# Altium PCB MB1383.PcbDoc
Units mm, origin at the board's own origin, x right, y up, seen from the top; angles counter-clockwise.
Board outline 35.5 x 65 mm, 2 copper layers (Top Layer, Bottom Layer), stack 1.57 mm thick; 78 components, 49 nets, 296 pads, 64 vias.
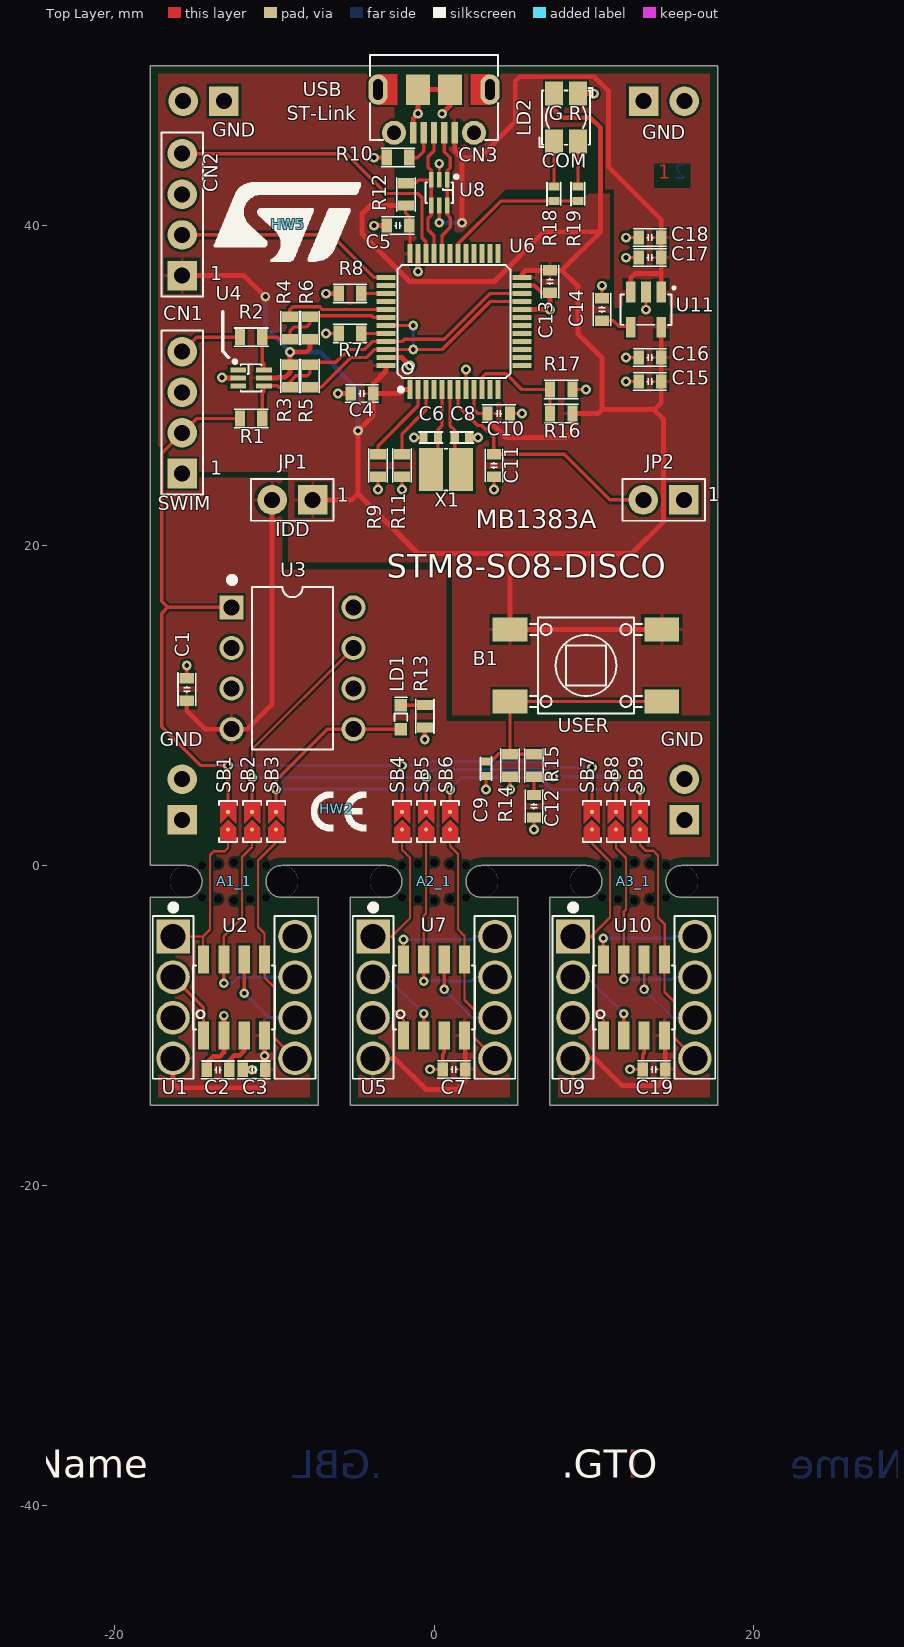
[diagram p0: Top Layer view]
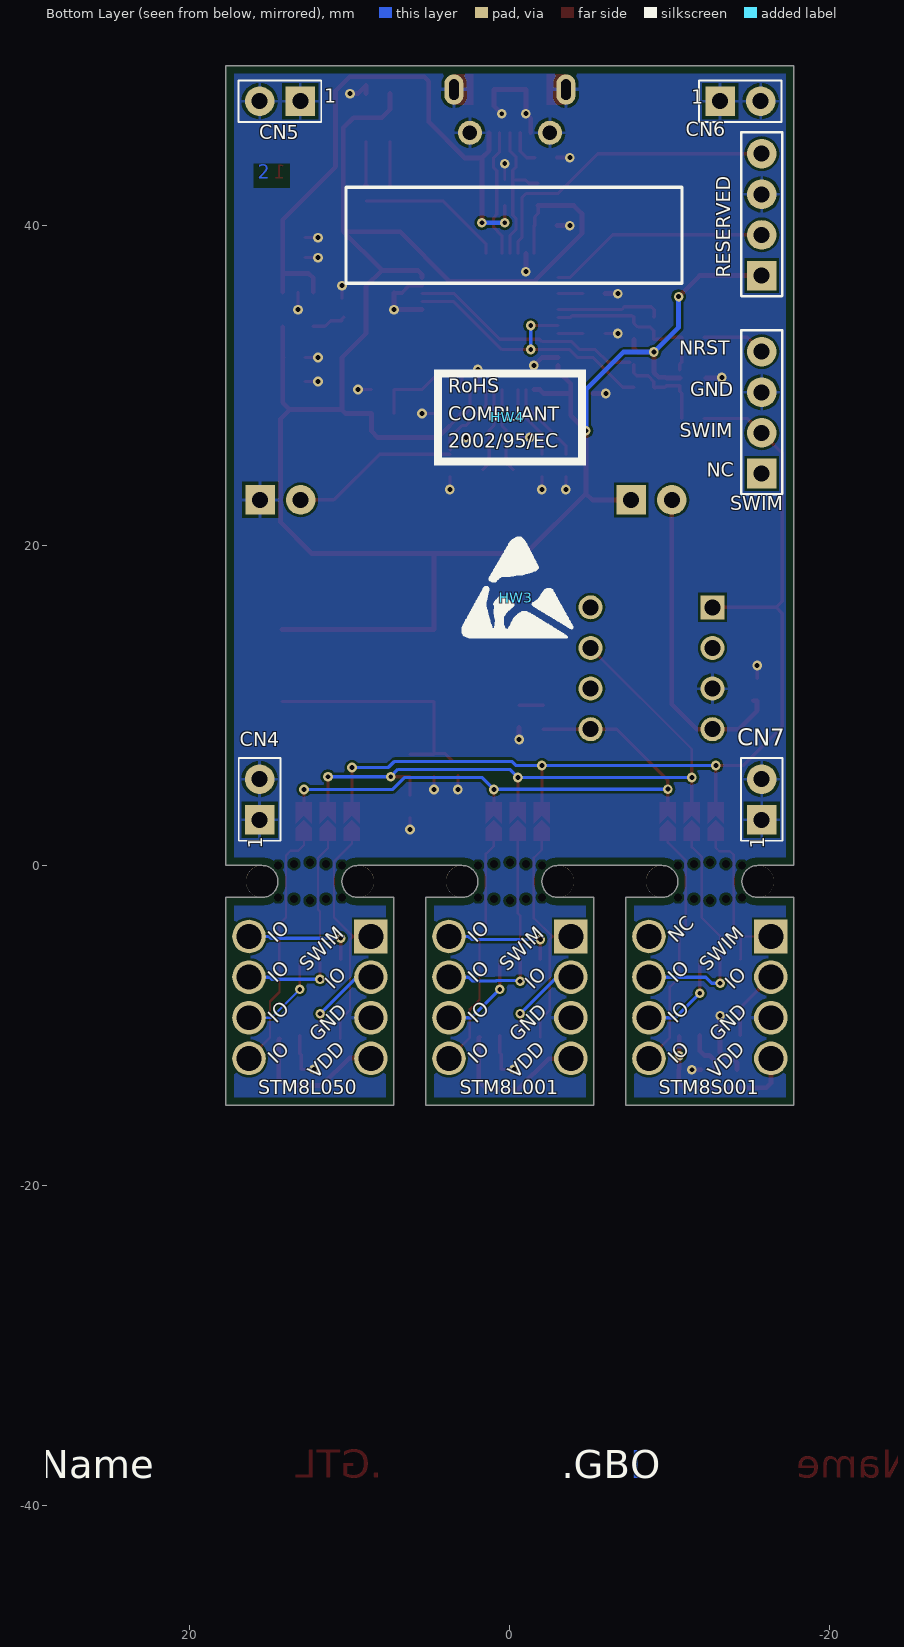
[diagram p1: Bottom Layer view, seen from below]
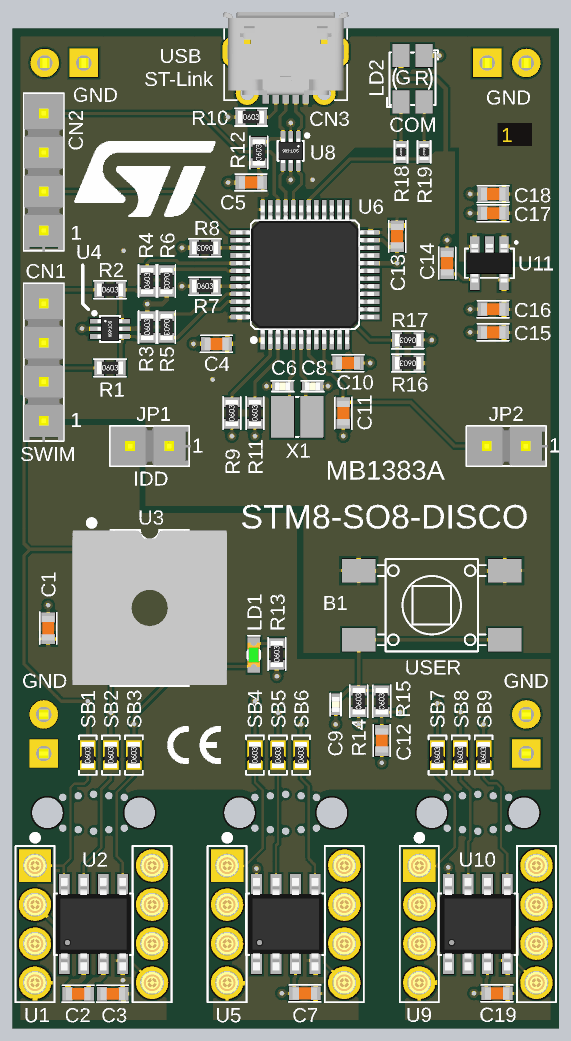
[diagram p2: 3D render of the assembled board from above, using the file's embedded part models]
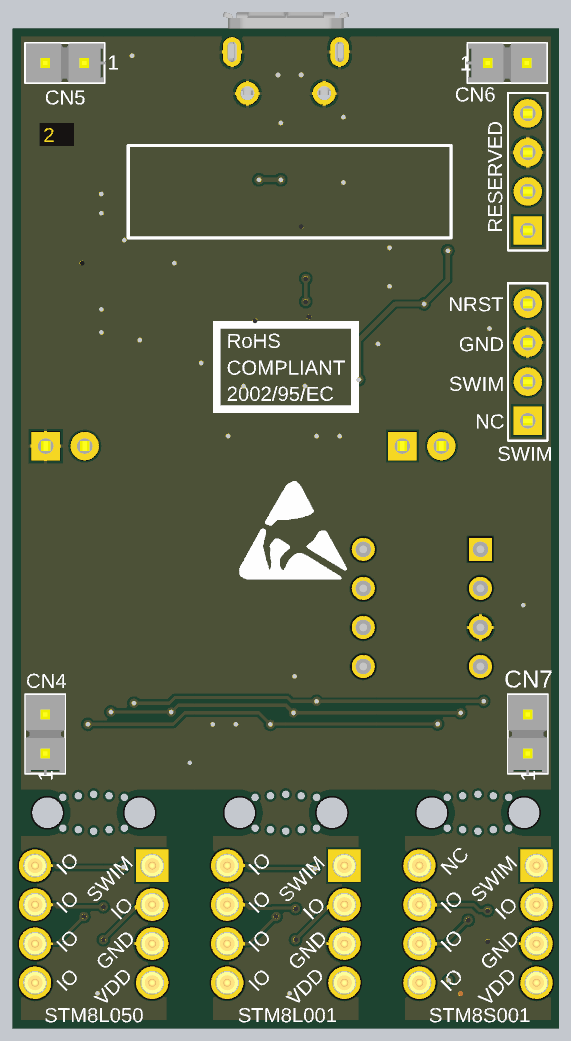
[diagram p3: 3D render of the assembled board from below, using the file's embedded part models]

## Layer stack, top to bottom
Top Solder: solder mask 0.015, Solder Resist, Dk 3.5
Top Layer: signal copper 0.035
Dielectric 1: dielectric 1.5, FR-4, Dk 4.8
Bottom Layer: signal copper 0.035
Bottom Solder: solder mask 0.015, Solder Resist, Dk 3.5

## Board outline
-17.75,-15 -17.75,-2 -15.5,-2 ccw(c-15.5,-1) -15.5,0 -17.75,0 -17.75,50 17.75,50 17.75,0 15.5,0 ccw(c15.5,-1) 15.5,-2 17.75,-2 17.75,-15 7.25,-15 7.25,-2 9.5,-2 ccw(c9.5,-1) 9.5,0 3,0 ccw(c3,-1) 3,-2 5.25,-2 5.25,-15 -5.25,-15 -5.25,-2 -3,-2 ccw(c-3,-1) -3,0 -9.5,0 ccw(c-9.5,-1) -9.5,-2 -7.25,-2 -7.25,-15

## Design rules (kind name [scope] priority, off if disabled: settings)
BoardOutlineClearance [All] p1: gap=0.2 ignorepadtopadclearanceinfootprint=FALSE except(0.5: Poly-OutlineEdge Poly-CavityEdge Poly-CutoutEdge Poly-SplitBarrior Poly-SplitContinuation)
Clearance Clearance_1 [InNetClass('MODULE') vs HasFootprint('ATTACHE')] p1: gap=0.15 ignorepadtopadclearanceinfootprint=FALSE except(0: Arc-Hole Track-Hole SMDPad-Hole THPad-Hole Via-Hole Fill-Hole Poly-Hole Region-Hole Text-Hole)
Clearance [All] p2: gap=0.15 ignorepadtopadclearanceinfootprint=FALSE except(0: Arc-Hole Track-Hole SMDPad-Hole THPad-Hole Via-Hole Fill-Hole Poly-Hole Region-Hole Text-Hole)
ComponentClearance [All] p1: gap=0.2 collisioncheckmode=3 verticalgap=0.2 showdistances=FALSE
DiffPairsRouting [All] p1: maxlimit=0.21 minlimit=0.21 mostfreqgap=0.21 toplayer_minwidth=0.21 toplayer_maxwidth=0.21 toplayer_prefwidth=0.21 bottomlayer_minwidth=0.21 bottomlayer_maxwidth=0.21 bottomlayer_prefwidth=0.21 maxuncoupledlength=12.7
HoleSize [All] p1: absolutevalues=TRUE maxlimit=10 minlimit=0.025 maxpercent=80.000 minpercent=20.000
HoleToHoleClearance [All] p1: gap=0.15 allowstackedmicrovias=TRUE
MinimumSolderMaskSliver [All] p1: minsoldermaskwidth=0.1
PlaneConnect [All] p1: planeconnectstyle=Relief reliefexpansion=0.508 reliefentries=4 reliefconductorwidth=0.21 reliefairgap=0.21
PolygonConnect PolygonConnect_via [IsVia] p1: connectstyle=Direct reliefconductorwidth=0.254 reliefentries=4 polygonreliefangle="90 Angle" airgapwidth=0.254
PolygonConnect [All] p2: connectstyle=Relief reliefconductorwidth=0.2 reliefentries=4 polygonreliefangle="90 Angle" airgapwidth=0.2
RoutingVias [All] p1: holewidth=0.3 width=0.6 viastyle="Through Hole" minholewidth=0.3 minwidth=0.6 maxholewidth=0.3 maxwidth=0.6
SilkToSilkClearance [All] p1: silktosilkclearance=0.2
SilkToSolderMaskClearance [IsPad] p1: minsilkscreentomaskgap=0.2 clearancetoexposedcopper=TRUE
SolderMaskExpansion [All] p1: expansion=0.102
UnpouredPolygon [All] p1: allowunpoured=TRUE allowshelved=TRUE
Width [All] p1: maxlimit=1 minlimit=0.15 preferedwidth=0.2 minimp=50.000000 maximp=50.000000 favimp=50.000000
21 further rules are at their usual default settings.

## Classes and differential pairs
component class U_STM8S001J3_Module: C2 C3 U1 U2
component class U_STM8L050J3_Module: C19 U9 U10
component class U_STM8L001J3_Module: C7 U5 U7
component class U_ST-LinkV2_SWIM: C4 C5 C6 C8 C10 C11 C13 C14 C15 C16 C17 C18 CN1 CN2 CN3 CN4 CN5 CN6 CN7 HW7 JP1 JP2 LD2 R1 R2 R3 R4 R5 R6 R7 R8 R9 R10 R11 R12 R16 R17 R18 R19 U4 U6 U8 U11 X1
component class U_Mechanical: HW2 HW3 HW4 HW5
component class U_Button-Led-ProgSocket: B1 C1 C9 C12 LD1 R13 R14 R15 SB1 SB2 SB3 SB4 SB5 SB6 SB7 SB8 SB9 U3
differential pair STLINK_USB_D: +STLINK_USB_D_P -STLINK_USB_D_N

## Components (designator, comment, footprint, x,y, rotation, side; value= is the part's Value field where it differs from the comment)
A1_1 "Comment" ATTACHE -12.5,-1 r0 top
A2_1 "Comment" ATTACHE 0,-1 r0 top
A3_1 "Comment" ATTACHE 12.5,-1 r0 top
B1 "SW-PUSH-CMS_BLUE" SWI_WEALTHMETAL_TD-0341_4P_BLUE 9.5,12.5 r270 top value=SW_BLUE
C1 "Capacitor" C0603 -15.45,11 r270 top value=1uF
C2 "Capacitor" C0603 -13.5,-12.775 r0 top value=1uF
C3 "Capacitor" C0603 -11.25,-12.775 r0 top value=100nF
C4 "Capacitor" C0603 -4.5,29.5 r0 top value=100nF
C5 "Capacitor" C0603 -2.25,40 r0 top value=100nF
C6 "Capacitor" C0402 -0.2,26.75 r180 top value=10pF
C7 "Capacitor" C0603 1.25,-12.75 r0 top value=100nF
C8 "Capacitor" C0402 1.75,26.75 r0 top value=10pF
C9 "Capacitor" C0402 3.25,6.05 r90 top value=10pF
C10 "Capacitor" C0603 4.05,28.25 r180 top value=100nF
C11 "Capacitor" C0603 3.75,25 r90 top value=100nF
C12 "Capacitor" C0603 6.25,3.7 r90 top value=100nF
C13 "Capacitor" C0603 7.25,36.5 r90 top value=100nF
C14 "Capacitor" C0603 10.5,34.75 r270 top value=10nF
C15 "Capacitor" C0603 13.5,30.25 r0 top value=1uF
C16 "Capacitor" C0603 13.5,31.75 r0 top value=100nF
C17 "Capacitor" C0603 13.5,38 r0 top value=100nF
C18 "Capacitor" C0603 13.5,39.25 r0 top value=1uF
C19 "Capacitor" C0603 13.75,-12.75 r0 top value=100nF
CN1 "Header 4" CON_SAMTEC_TSW-104-07-G-S -15.74,28.31 r90 top
CN2 "Header 4" CON_SAMTEC_TSW-104-07-G-S -15.74,40.685 r90 top
CN3 "USB_uB_105017.0001" CON_USBMICROB_MOLEX_105017-0001_H2P90 0,49.95 r180 top value=USB_uB_105017-0001
CN4 "Jumper_Header 2x1" CON_SAMTEC_TSW-102-07-G-S 15.65,4.125 r90 bottom value="Shunt not fitted"
CN5 "Jumper_Header 2x1" CON_SAMTEC_TSW-102-07-G-S 14.376,47.775 r0 bottom value="Shunt not fitted"
CN6 "Jumper_Header 2x1" CON_SAMTEC_TSW-102-07-G-S -14.405,47.775 r180 bottom value="Shunt not fitted"
CN7 "Jumper_Header 2x1" CON_SAMTEC_TSW-102-07-G-S -15.74,4.125 r90 bottom value="Shunt not fitted"
HW2 "Logo" LOGO_CE -6.075,3.55 r0 top value="LOGO CE"
HW3 "Logo" LOGO_MAIN_1 -0.394,16.75 r180 bottom value="LOGO ESD"
HW4 "Logo" LOGO_ROHS 0.123,28.025 r180 bottom value="LOGO ROHS"
HW5 "Logo" LOGO_STM -9.1,40.075 r0 top value="LOGO ST"
JP1 "Jumper_Header 2x1" CON_SAMTEC_TSW-102-07-G-S -8.85,22.85 r180 top value="Shunt not fitted"
JP2 "Jumper_Header 2x1" CON_SAMTEC_TSW-102-07-G-S 14.35,22.85 r180 top value="Shunt not fitted"
LD1 "LED_green" LED_0603_GREEN -2.075,9.265 r90 top value=GREEN
LD2 "LD_BICOLOR_CMS" LED_BI-GR_HSMF-A201-A00J1 8.25,46.75 r180 top
R1 "Resistor" R0603 -11.43,27.94 r0 top value=47R
R2 "Resistor" R0603 -11.43,33.02 r0 top value=47R
R3 "Resistor" R0603 -9,30.595 r90 top value=680R
R4 "Resistor" R0603 -9,33.595 r90 top value=220R
R5 "Resistor" R0603 -7.75,30.595 r270 top value=220R
R6 "Resistor" R0603 -7.75,33.595 r270 top value=680R
R7 "Resistor" R0603 -5.25,33.25 r0 top value=100K
R8 "Resistor" R0603 -5.25,35.75 r180 top value=4K7
R9 "Resistor" R0603 -3.5,25 r90 top value=10K
R10 "Resistor" R0603 -2.25,44.25 r0 top value=100K
R11 "Resistor" R0603 -2,25 r90 top value=10K
R12 "Resistor" R0603 -1.75,41.95 r90 top value=1K5
R13 "Resistor" R0603 -0.575,9.325 r90 top value=510R
R14 "Resistor" R0603 4.75,6.25 r90 top value=100K
R15 "Resistor" R0603 6.25,6.25 r90 top value=1K
R16 "Resistor" R0603 7.95,28.25 r180 top value=4K7
R17 "Resistor" R0603 7.95,29.75 r180 top value=4K7
R18 "Resistor" R0402 7.5,41.984 r270 top value=330R
R19 "Resistor" R0402 9,41.984 r270 top value=330R
SB1 "SB_ON" SOLDER-BRIDGE_R0603-0R -12.875,2.75 r90 top
SB2 "SB_ON" SOLDER-BRIDGE_R0603-0R -11.375,2.75 r90 top
SB3 "SB_ON" SOLDER-BRIDGE_R0603-0R -9.875,2.75 r90 top
SB4 "SB_OFF" SOLDER-BRIDGE_R0603-0R -2,2.75 r90 top
SB5 "SB_OFF" SOLDER-BRIDGE_R0603-0R -0.5,2.75 r90 top
SB6 "SB_OFF" SOLDER-BRIDGE_R0603-0R 1,2.75 r90 top
SB7 "SB_OFF" SOLDER-BRIDGE_R0603-0R 9.875,2.75 r90 top
SB8 "SB_OFF" SOLDER-BRIDGE_R0603-0R 11.375,2.75 r90 top
SB9 "SB_OFF" SOLDER-BRIDGE_R0603-0R 12.875,2.75 r90 top
U1 "DIL8-LYCONN-7.40X1.83" CON_LYCONN_DIL8_7P40X1P83_P254 -12.5,-8.25 r0 top value=DIL8-LYCONN--7.40X1.83
U2 "STM8S001J3M3" ICC_SO8_5X4_P127 -12.5,-8.25 r0 top
U3 "STM8-MODULE-DIL8-SOCKET" DIP8 -8.85,12.325 r0 top value=508-AG10D
U4 "USBLC6-2P6" ESD_SOT666 -11.43,30.48 r270 top
U5 "DIL8-LYCONN-7.40X1.83" CON_LYCONN_DIL8_7P40X1P83_P254 0,-8.25 r0 top value=DIL8-LYCONN--7.40X1.83
U6 "STM32F103CBT6" ICC_LQFP48_7X7_P050 1.25,34 r0 top
U7 "STM8L001J3M3" ICC_SO8_5X4_P127 0,-8.25 r0 top
U8 "USBLC6-2P6" ESD_SOT666 0.325,42.055 r180 top
U9 "DIL8-LYCONN-7.40X1.83" CON_LYCONN_DIL8_7P40X1P83_P254 12.5,-8.25 r0 top value=DIL8-LYCONN--7.40X1.83
U10 "STM8L050J3M3" ICC_SO8_5X4_P127 12.5,-8.25 r0 top
U11 "LD3985M33R" REG_SOT23-5L 13.25,34.75 r180 top
X1 "XTAL_2_PINS" CRY_NX3225GD_2P 0.75,24.75 r180 top value=NX3225GD-8.00M

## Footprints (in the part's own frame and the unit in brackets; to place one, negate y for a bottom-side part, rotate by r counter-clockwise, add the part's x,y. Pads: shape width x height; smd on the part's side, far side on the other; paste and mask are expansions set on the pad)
ATTACHE [mm]
  round 0 hole 0.5 unplated: 1(-2,-1) 1(2,1) 2(-1,-1.1) 2(1,1.1) 3(0,-1.2) 3(0,1.2) 4(-1,1.1) 4(1,-1.1) 5(-2,1) 5(2,-1)
  round 2 hole 2 unplated paste+0: 6(-3,0) 7(3,0)
C0402 [mm]
  rect 0.51x0.56 smd mask+0.05: 1(-0.45,0) 2(0.45,0)
  silkscreen extent -0.72,-0.35 0.72,0.35, body extent -0.5,-0.3 0.5,0.3, height 0.4
C0603 [mm]
  rect 0.64x0.89 smd mask+0.05: 1(-0.7,0) 2(0.7,0)
  silkscreen extent -1.05,-0.55 1.02,0.55, body extent -0.9,-0.5 0.9,0.5, height 1.4
CON_LYCONN_DIL8_7P40X1P83_P254 [mm] "DIL8 LYCONN 7.40x1.83"
  rect 2.1x2.1 hole 1.55 mask+0.05: 1(-3.81,3.81)
  round 2.1 hole 1.55: 2(-3.81,1.27) 3(-3.81,-1.27) 4(-3.81,-3.81) 5(3.81,-3.81) 6(3.81,-1.27) 7(3.81,1.27) 8(3.81,3.81)
  silkscreen extent -5.08,-5.08 5.08,5.08, body extent -4.52,-4.52 4.52,4.52, height 0.43
CON_SAMTEC_TSW-102-07-G-S [mm]
  rect 1.85x1.85 / inner round 1.85 / far side rect 1.85x1.85 hole 1 mask+0.05: 1(-1.27,0)
  round 1.85 hole 1 mask+0.05: 2(1.27,0)
  silkscreen extent -2.58,-1.3 2.58,1.3, body extent -2.67,-1.3 2.58,1.3, height 8.38
CON_SAMTEC_TSW-104-07-G-S [mm]
  rect 1.85x1.85 / inner round 1.85 / far side rect 1.85x1.85 hole 1 mask+0.05: 1(-3.81,0)
  round 1.85 hole 1 mask+0.05: 2(-1.27,0) 3(1.27,0) 4(3.81,0)
  silkscreen extent -5.12,-1.3 5.12,1.3, body extent -5.21,-1.37 5.18,1.37, height 8.38
CON_USBMICROB_MOLEX_105017-0001_H2P90 [mm]
  rect 0.4x1.35 smd mask+0.05: 1(-1.3,4.15) 2(-0.65,4.15) 3(0,4.15) 4(0.65,4.15) 5(1.3,4.15)
  round 1.5 hole 0.9 mask+0.05: 6(-2.5,4.15) 7(2.5,4.15)
  oval 1.2x1.9 hole 0.6 slot 1.3 at 90 deg mask+0.05: 8(3.5,1.45) 9(-3.5,1.45)
  rect 1.5x1.9 smd mask+0.05: 10(-1,1.45) 11(1,1.45)
  Top Layer region: 2.3,2.4 3.5,2.4 3.5,0.5 2.3,0.5 2.3,2.4
  Top Layer region: -3.5,2.4 -2.3,2.4 -2.3,0.5 -3.5,0.5 -3.5,2.4
  silkscreen extent -4,-0.7 4,4.6, body extent -4.1,-1.15 4.1,4.66, height 2.9
CRY_NX3225GD_2P [mm]
  rect 1.5x2.7 smd mask+0.05: 1(-0.95,0) 2(0.95,0)
  silkscreen extent -0.1,-1.3 0.1,1.3, body extent -1.65,-1.3 1.65,1.3, height 1
DIP8 [mm]
  rect 1.5x1.5 hole 1: 1(-3.81,3.81)
  round 1.5 hole 1: 2(-3.81,1.27) 3(-3.81,-1.27) 4(-3.81,-3.81) 5(3.81,-3.81) 6(3.81,-1.27) 7(3.81,1.27) 8(3.81,3.81)
  silkscreen extent -2.54,-5.08 2.54,5.08, body extent -5.03,-5.03 5.03,5.03, height 8
ESD_SOT666 [mm]
  rect 0.3x0.99 smd mask+0.05: 1(-0.5,-0.805) 2(0,-0.805) 3(0.5,-0.805) 4(0.5,0.805) 5(0,0.805) 6(-0.5,0.805)
  silkscreen extent -0.85,-0.65 0.85,0.65, body extent -0.85,-0.8 0.85,0.8, height 0.6
ICC_LQFP48_7X7_P050 [mm]
  rect 0.3x1.2 smd mask+0.05: 1(-2.75,-4.25) 2(-2.25,-4.25) 3(-1.75,-4.25) 4(-1.25,-4.25) 5(-0.75,-4.25) 6(-0.25,-4.25) 7(0.25,-4.25) 8(0.75,-4.25) 9(1.25,-4.25) 10(1.75,-4.25) 11(2.25,-4.25) 12(2.75,-4.25) 25(2.75,4.25) 26(2.25,4.25) 27(1.75,4.25) 28(1.25,4.25) 29(0.75,4.25) 30(0.25,4.25) 31(-0.25,4.25) 32(-0.75,4.25) 33(-1.25,4.25) 34(-1.75,4.25) 35(-2.25,4.25) 36(-2.75,4.25)
  rect 1.2x0.3 smd mask+0.05: 13(4.25,-2.75) 14(4.25,-2.25) 15(4.25,-1.75) 16(4.25,-1.25) 17(4.25,-0.75) 18(4.25,-0.25) 19(4.25,0.25) 20(4.25,0.75) 21(4.25,1.25) 22(4.25,1.75) 23(4.25,2.25) 24(4.25,2.75) 37(-4.25,2.75) 38(-4.25,2.25) 39(-4.25,1.75) 40(-4.25,1.25) 41(-4.25,0.75) 42(-4.25,0.25) 43(-4.25,-0.25) 44(-4.25,-0.75) 45(-4.25,-1.25) 46(-4.25,-1.75) 47(-4.25,-2.25) 48(-4.25,-2.75)
  silkscreen extent -3.52,-3.52 3.52,3.52, body extent -4.5,-4.5 4.5,4.5, height 1.6
ICC_SO8_5X4_P127 [mm]
  rect 0.7x1.75 smd mask+0.05: 1(-1.905,-2.375) 2(-0.635,-2.375) 3(0.635,-2.375) 4(1.905,-2.375) 5(1.905,2.375) 6(0.635,2.375) 7(-0.635,2.375) 8(-1.905,2.375)
  silkscreen extent -2.58,-2 2.58,2, body extent -2.57,-3 2.57,3, height 1.75
LED_0603_GREEN [mm]
  rect 0.8x0.8 smd mask+0.05: 1(-0.75,0) 2(0.75,0)
  silkscreen extent -0.25,-0.4 1.25,0.4, body extent -0.8,-0.4 0.8,0.4, height 0.6
LED_BI-GR_HSMF-A201-A00J1 [mm]
  rect 1.1x1.5 smd mask+0.05: 1(-0.75,-1.5) 2(-0.75,1.5) 3(0.75,1.5) 4(0.75,-1.5)
  silkscreen extent -1.65,-1.85 1.65,1.85, body extent -1.5,-1.85 1.5,1.85, height 2.1
LOGO_CE [mm]
  silkscreen extent -1.61,-1.37 1.85,1.07
LOGO_MAIN_1 [mm]
  silkscreen extent -3.36,-2.51 3.52,3.76
LOGO_ROHS [mm]
  silkscreen extent -4.63,-3.02 4.87,2.98
LOGO_STM [mm]
  silkscreen extent -4.66,-2.3 4.54,2.62
R0402 [mm]
  rect 0.51x0.7 smd mask+0.05: 1(-0.45,0) 2(0.45,0)
  silkscreen extent -0.72,-0.43 0.72,0.43, body extent -0.52,-0.3 0.52,0.3, height 0.4
R0603 [mm]
  rect 0.64x1 smd mask+0.05: 1(-0.7,0) 2(0.7,0)
  silkscreen extent -1.05,-0.58 1.05,0.58, body extent -0.9,-0.5 0.9,0.5, height 0.56
REG_SOT23-5L [mm]
  rect 0.6x1.3 smd mask+0.05: 1(-0.95,-1.1) 2(0,-1.1) 3(0.95,-1.1) 4(0.95,1.1) 5(-0.95,1.1)
  silkscreen extent -1.6,-0.95 1.6,0.97, body extent -1.52,-1.25 1.52,1.25, height 1.1
SOLDER-BRIDGE_R0603-0R [mil]
  round 10 smd paste-393.7: 1(-19.68,0) 2(23.62,0)
  Top Layer region: -5.91,19.68 13.78,0 -5.91,-19.68 47.24,-19.68 47.24,19.68 -5.91,19.68
  Top Layer region: -47.24,-19.68 -47.24,19.68 -15.75,19.68 3.94,0 -15.75,-19.68 -47.24,-19.68
  silkscreen extent -50,-23 50,23, body extent -36,-20 36,20, height 22
SWI_WEALTHMETAL_TD-0341_4P_BLUE [mm]
  rect 1.52x2.16 smd mask+0.05: 1(-2.25,-4.75) 2(-2.25,4.75) 3(2.25,-4.75) 4(2.25,4.75)
  silkscreen extent -3,-3.5 3,3.5, body extent -3,-5.15 3,5.15, height 7.55

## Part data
B1: library part MCD-00002, "Non-Open Push-Button 0.1A 24V BLUE", Manufacturer=WEALTHMETAL, Manufacturer_Part_Number=TD0341X-G01-BLU
C1 C2 C15 C18: library part MCD-00010, "Capacitor, MLCC, 1uF, 16V, X5R, 10%, 0603, T=0,8mm", Manufacturer=YAGEO, Manufacturer_Part_Number=CC0603KRX5R7BB105, Package=C0603
C3 C4 C5 C7 C10 C11 C12 C13 C16 C17 C19: library part MCD-00211, "Capacitor, MLCC, 100nF, 16V, X7R, 10%, 0603, T=0,8mm", Manufacturer=YAGEO, Manufacturer_Part_Number=CC0603KRX7R7BB104, Package=C0603
C6 C8 C9: library part MCD-00015, "Capacitor, MLCC, 10pF, 50V, NPO, 5%, 0402, T=0,5mm", Manufacturer=YAGEO, Manufacturer_Part_Number=CC0402JRNPO9BN100, Package=C0402
C14: library part MCD-00017, "Capacitor, MLCC, 10nF, 50V, X7R, 10%, 0603, T=0.8mm", Manufacturer=YAGEO, Manufacturer_Part_Number=CC0603KRX7R9BB103, Package=C0603
CN1 CN2: "Header, 4-Pin", Manufacturer=SAMTEC, Manufacturer_Part_Number=TSW-104-07-G-S
CN3: library part MCD-00028, "USB-MICRO-B, 0.65mm, RA, SMT, Bottom Mount,", Manufacturer=MOLEX, Manufacturer_Part_Number=1050170001
CN4 CN5 CN6 CN7 JP1 JP2: library part MCD-00045, "Header, 2x1, 2,54mm, VR, TH, Height 5.84mm/2.54mm", Manufacturer=SAMTEC, Manufacturer_Part_Number=TSW-102-07-x-S
HW2: library part MCD-00626, "CE logo footprint for PCB"
HW3: library part MCD-00627, "Hand ESD logo footprint for PCB", Manufacturer=n/a
HW4: library part MCD-00628, "ROHS logo footprint for PCB"
HW5: library part MCD-00625, "STMicroelectronics logo footprint for PCB", Manufacturer=n/a
LD1: library part MCD-00050, "LED, Green, 0603", Manufacturer=EVERLIGHT, Manufacturer_Part_Number=19-213SYGC/S530-E2/TR8, Package="LED 0603"
LD2: library part MCD-00051, "LED Bicolor", Alternate_Manufacturer=EVERLUCK, Alternate_Manufacturer_Part_Number=LE-RGW35280, Manufacturer="AVAGO TECHNOLOGIES", Manufacturer_Part_Number=HSMF-A201-A00J1
R1 R2: library part MCD-00482, "Resistor,47R,0603,1%,1/10W", Manufacturer=YAGEO, Manufacturer_Part_Number=RC0603FR-0747RL, Package=R0603
R3 R6: library part MCD-00508, "Resistor,680R,0603,1%,1/10W", Manufacturer=YAGEO, Manufacturer_Part_Number=RC0603FR-07680RL, Package=R0603
R4 R5: library part MCD-00428, "Resistor,220R,0603,1%,1/10W", Manufacturer=YAGEO, Manufacturer_Part_Number=RC0603FR-07220RL, Package=R0603
R7 R10 R14: library part MCD-00223, "Resistor,100K,0603,1%,1/10W", Manufacturer=YAGEO, Manufacturer_Part_Number=RC0603FR-07100KL, Package=R0603
R8 R16 R17: library part MCD-00219, "Resistor,4K7,0603,1%,1/10W", Manufacturer=YAGEO, Manufacturer_Part_Number=RC0603FR-074K7L, Package=R0603
R9 R11: library part MCD-00220, "Resistor,10K,0603,1%,1/10W", Manufacturer=YAGEO, Manufacturer_Part_Number=RC0603FR-0710KL, Package=R0603
R12: library part MCD-00217, "Resistor,1K5,0603,1%,1/10W", Manufacturer=YAGEO, Manufacturer_Part_Number=RC0603FR-071K5L, Package=R0603
R13: library part MCD-00225, "Resistor,510R,0603,1%,1/10W", Manufacturer=YAGEO, Manufacturer_Part_Number=RC0603FR-07510RL, Package=R0603
R15: library part MCD-00070, "Resistor,1K,0603,1%,1/10W", Manufacturer=YAGEO, Manufacturer_Part_Number=RC0603FR-071KL, Package=R0603
R18 R19: library part MCD-00062, "Resistor,330R,0402,1%,1/16W", Manufacturer=YAGEO, Manufacturer_Part_Number=RC0402FR-07330RL, Package=R0402
SB1 SB2 SB3: library part MCD-00071, "Solder Bridge ON"
SB4 SB5 SB6 SB7 SB8 SB9: library part MCD-00072, "Solder Bridge OFF"
U1 U5 U9: library part MCD-01221, "PCB socket DIL 8-pin", Manufacturer=LYCONN, Manufacturer_Part_Number=DIL8-LYCONN--7.40X1.83
U2: library part MCD-01218, "STM8S 8-bit MCU, 8-Kbyte Flash, 128-byte data EEPROM", Manufacturer=STMICROELECTRONICS, Package=SO8N
U3: "STM8-MODULE-DIL8-", Manufacturer="TE CONNECTIVITY / AMP", Manufacturer_Part_Number=508-AG10D
U4 U8: library part MCD-00169, "USB OTG FS ESD protection", Manufacturer=STMICROELECTRONICS
U6: library part MCD-00085, "Medium-density performance line ARM-based 32-bit MCU with 128KB Flash", Manufacturer=STMICROELECTRONICS
U7: library part MCD-01217, "STM8L 8-bit ultra-low-power microcontroller, 8-Kbyte Flash", Manufacturer=STMICROELECTRONICS, Package=SO8N
U10: library part MCD-01216, "STM8L 8-bit ultra-low-power MCU, 8-Kbyte Flash, 256-byte data EEPROM", Manufacturer=STMICROELECTRONICS, Package=SO8N
U11: library part MCD-00086, "Ultra low drop-low noise BiCMOS voltage, regulators low ESR capacitors compatible", Manufacturer=STMICROELECTRONICS
X1: library part MCD-00092, "Crystal 8Mhz, 8pF, -+50PPM, SMD", Manufacturer=NDK, Manufacturer_Part_Number="NX3225GD 8MHz EXS00A-CG04874"

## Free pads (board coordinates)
  round 0.508 on Mech16: 1(-22.05,-45.212) 1(26.797,-45.212)

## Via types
v1: diameter 0.6, hole 0.3, Top Layer to Bottom Layer, tented both sides, 64 vias

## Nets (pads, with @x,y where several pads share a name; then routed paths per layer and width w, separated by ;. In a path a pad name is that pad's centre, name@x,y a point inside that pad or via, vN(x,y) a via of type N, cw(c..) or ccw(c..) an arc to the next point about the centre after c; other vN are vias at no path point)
3V3_STLINK: B1.1 B1.2 C4.2 C5.2 C10.2 C13.2 C15.2 C16.2 CN2.1 JP1.1 LD2.4 R3.2 R6.2 R12.1 R16.1 U4.5 U6.1 U6.9 U6.24 U6.36 U6.48 U11.5 | length 151.8
  Top Layer w0.21: R12.1 -1.778,41.222 -1.778,40.767 -1.55,40.539 C5.2 -1.5,39.95 U6.36 ; U6.9 2.5,28.5 2.75,28.25 3.125,28.25 3.125,28.125 3.812,27.438
  Top Layer w0.3: CN2.1 -11.856,36.875 v1(-10.541,35.56) ; U4.5 -9.779,30.48 -9.744,30.515 -9.301,30.515 -9,30.816 R3.2 v1(-9,32.095) -8,32.095 -7.75,32.345 R6.2 ; JP1.1@-7.98,22.85 JP1.1 -5.15,22.85 -4.75,23.25 ; U6.48 -3,30.909 -3.8,30.109 C4.2 ; R12.1 -4,41.25 -4.5,40.75 -4.5,39.5 -2.5,37.5 -1.5,36.5 3.75,36.5 6.869,39.619 10.414,39.619 ; U6.1 -1.873,29.75 -2.123,29.5 C4.2 ; 3.812,27.438 4.5,26.75 8.25,26.75 8.65,27.15 R16.1 10.25,28.25 10.5,28.5 ; U6.24 5.5,36.95 5.75,37.2 C13.2 7.995,37.2 ; LD2.4 7.5,47.237 8.001,46.736 9.779,46.736 10.414,46.101 10.414,39.619 ; U11.5 14.2,31.77 14.19,31.76 C16.2 C15.2 14.2,28.925 13.775,28.5 13.75,28.5 ; B1.2 B1.1 4.75,19.5 ; -4.75,23.25 -1,19.5 4.75,19.5 ; -4.75,23.25 v1(-4.75,27.178) -3.8,28.128 C4.2 ; 4.75,19.5 12.375,19.5 14.35,21.475 14.35,27.9 13.75,28.5 ; 7.995,37.2 10.414,39.619 ; 7.995,37.2 9,36.195 9,33.25 10.5,31.75 10.5,28.5 ; 10.5,28.5 13.75,28.5
  Bottom Layer w0.3: v1(-10.541,35.56) -10.541,33.636 v1(-9,32.095) -7.095,32.095 -4.75,29.75 v1(-4.75,27.178)
5V_STLINK: C17.2 C18.2 CN3.1 U8.5 U11.1 U11.3 | length 38.4
  Top Layer w0.21: v1(0.325,40.175) U8.5
  Top Layer w0.3: CN3.1 1.3,44.674 1.75,44.224 ; v1(1.75,40.175) 1.75,44.224 ; U11.3 12.3,36.727 12.573,37 14.2,37 ; U11.1 14.2,37 ; C17.2 C17.2@14.2,38.085 ; 1.75,44.224 2.822,44.224 5.08,46.482 5.08,49.022 5.358,49.3 10.025,49.3 10.9,48.425 10.9,43.675 14.2,40.375 C18.2 C17.2@14.2,38.085 ; 14.2,37 C17.2@14.2,38.085
  Bottom Layer w0.3: v1(0.325,40.175) 1.675,40.175 v1@1.75,40.25
AIN_1: R16.2 R17.2 U6.10 | length 7
  Top Layer w0.21: U6.10 3,30.5 3.234,30.734 4.516,30.734 5.5,29.75 R17.2 R16.2
GND: C1.1 C2.1 C3.1 C4.1 C5.1 C6.2 C7.1 C8.2 C9.1 C10.1 C11.1 C12.1 C13.1 C14.1 C15.1 C16.1 C17.1 C18.1 C19.1 CN1.3 CN2.3 CN3.5 CN3.6 CN3.7 CN3.8 CN3.9 CN3.10 CN3.11 CN4.1 CN4.2 CN5.1 CN5.2 CN6.1 CN6.2 CN7.1 CN7.2 JP2.1 LD2.1 R7.1 R8.2 R9.1 R10.1 R11.1 R13.1 R14.1 R17.1 U1.3 U2.2 U3.3 U4.2 U5.3 U6.8 U6.20 U6.23 U6.35 U6.47 U7.3 U8.2 U9.3 U10.3 U11.2 | length 47.9
  Top Layer w0.15: U8.2 v1(0.325,43.875)
  Top Layer w0.21: C1.1 v1(-15.45,12.5) ; v1(-6.75,33.25) R7.1 ; v1(-3.5,23.5) R9.1 ; v1(-2,23.5) R11.1 ; v1(-1.25,26.75) C6.2 ; v1(-0.25,-12.75) C7.1 0.55,-11.787 0.635,-11.702 U7.3 ; U6.8 v1(2,31) ; C8.2 v1(2.75,26.75) ; v1(3.25,4.75) C9.1 ; v1(3.75,23.5) C11.1 ; v1(4.75,4.75) R14.1 ; C10.1 v1(5.5,28.25) ; v1(6.25,2.25) C12.1 ; R17.1 v1(9.5,29.75) ; C14.1 v1(10.5,36.25) ; v1(12,30.25) C15.1 ; v1(12,31.75) C16.1 ; v1(12,38) C17.1 ; v1(12,39.25) C18.1 ; v1(12.25,-12.75) C19.1 13.05,-11.842 13.135,-11.757 U10.3 ; v1(13.25,34.75) U11.2
  Top Layer w0.25: v1(-3.75,44.25) R10.1 ; U6.23 6.295,36.25 6.745,35.8 C13.1
  Top Layer w0.3: C2.1 -14.2,-12.324 -13.826,-11.95 -13.4,-11.95 -13.135,-11.685 U2.2 v1(-13.135,-9.385) ; v1(-13.25,30.5) -13.23,30.48 U4.2 ; C3.1 v1(-11.375,-12.775) ; v1(-6.75,35.75) R8.2 ; v1(-6,29.5) C4.1 ; v1(-3.75,40) C5.1 ; U6.47 -2,31.75 -1.75,31.5 v1(-1.5,31.25) ; CN3.5 -1.3,46.7 v1(-1,47) CN3.11 CN3.10 1,47.482 v1(0.508,46.99) ; v1(-1,37.125) U6.35 ; v1(-0.575,7.875) R13.1 ; U6.20 v1(7.25,34.75) C13.1 ; LD2.1 9,48.75 9.5,48.25 v1(10,48.25)
LED_STLINK: R18.2 R19.2 U6.30 | length 9.2
  Top Layer w0.21: U6.30 1.5,38.861 4.173,41.534 R18.2 R19.2
NetB1_3: B1.3 B1.4 C9.2 R14.2 R15.2 | length 16.6
  Top Layer w0.21: C9.2 3.564,6.5 4.064,7 R14.2@4.75,7 ; R15.2 R14.2 ; B1.4 B1.3 4.75,7.5 ; R14.2 R14.2@4.75,7 ; R14.2 4.75,7.5 ; R14.2@4.75,7 4.75,7.5
NetC2_2: C2.2 U2.3 | length 2.7
  Top Layer w0.3: C2.2 -12.8,-12.2 -12.475,-11.875 -12.15,-11.875 -11.865,-11.59 U2.3
NetC12_2: C12.2 R15.1 SB2.2 SB5.2 SB8.2 U3.7 | length 42.8
  Top Layer w0.15: -11.375,6.3 -11.375,7.26 U3.7
  Top Layer w0.21: SB2.2 -11.375,6.3 ; SB5.2 v1(-0.5,5.5) ; C12.2 R15.1 v1(7.45,5.55) ; SB8.2 v1(11.375,5.55)
  Bottom Layer w0.21: v1(-11.375,5.5) v1(-0.5,5.5) 0,6 7,6 v1(7.45,5.55) v1(11.375,5.55) v1@11.5,5.55
NetC14_2: C14.2 U11.4 | length 2.2
  Top Layer w0.21: C14.2@10.38,34.265 C14.2@10.595,34.05 ; C14.2 C14.2@10.595,34.05 ; U11.4@12.29,33.695 11.557,33.695 11.202,34.05 C14.2@10.595,34.05
NetCN1_4: CN1.4 R2.1 | length 4
  Top Layer w0.21: CN1.4 -14.84,33.02 R2.1
NetCN3_4: CN3.4 R10.2 | length 2.2
  Top Layer w0.21: R10.2 -1.05,44.25 -0.65,44.65 CN3.4
NetLD1_1: LD1.1 SB3.2 SB6.2 SB9.2 U3.5 | length 37.5
  Top Layer w0.21: SB3.2 v1(-9.875,4.775) -9.875,5.325 -6.685,8.515 U3.5 LD1.1 ; SB6.2@1,3.25 SB6.2 v1(1,4.75) ; SB9.2 v1(12.875,4.75)
  Bottom Layer w0.21: v1(-9.875,4.775) v1@1.025,4.775 ; v1(1,4.75) v1@1.025,4.775 ; v1@1.175,4.775 v1@1.025,4.775 ; v1(12.875,4.75) 7.315,4.75 6.565,5.5 1.75,5.5 v1@1.025,4.775
NetLD1_2: LD1.2 R13.2 | length 1.5
  Top Layer w0.21: LD1.2 R13.2@-0.575,10.015
NetLD2_2: LD2.2 R19.1 | length 2.7
  Top Layer w0.21: R19.1@9,42.544 LD2.2
  Top Layer w0.3: R19.1@9,42.544 R19.1@9.005,42.539
NetLD2_3: LD2.3 R18.1 | length 2.8
  Top Layer w0.21: R18.1 LD2.3
NetR7_2: R7.2 U6.44 | length 1.5
  Top Layer w0.21: R7.2 U6.44
NetR8_1: R8.1 U6.39 | length 1.5
  Top Layer w0.21: R8.1 U6.39
NetR9_2: R9.2 U6.2 | length 5.1
  Top Layer w0.21: R9.2 -3.5,26.25 -1,28.75 U6.2
NetR11_2: R11.2 U6.3 | length 4.7
  Top Layer w0.21: R11.2 -2,27 -0.5,28.5 U6.3
NetU1_2: U1.2 U2.1 | length 4.4
  Top Layer w0.21: U1.2 -14.405,-8.885 U2.1
NetU1_6: U1.6 U2.6 | length 5.9
  Top Layer w0.21: v1(-11.865,-7.99) U2.6
  Bottom Layer w0.21: v1(-11.865,-7.99) -10.335,-9.52 U1.6
NetU5_2: U5.2 U7.2 | length 5.5
  Top Layer w0.21: U7.2 v1(-0.635,-9.26)
  Bottom Layer w0.21: U5.2 -2.915,-6.98 v1(-0.635,-9.26)
NetU5_6: U5.6 U7.6 | length 5.8
  Top Layer w0.21: v1(0.635,-7.75) U7.6
  Bottom Layer w0.21: v1(0.635,-7.75) 2.405,-9.52 U5.6
NetU5_8: U5.8 U7.8 | length 7
  Top Layer w0.21: U7.8 v1(-1.905,-4.63)
  Bottom Layer w0.21: v1(-1.905,-4.63) 2.37,-4.63 2.56,-4.44 U5.8
NetU9_2: U9.2 U10.2 | length 5.5
  Top Layer w0.21: U10.2 v1(11.865,-9.265)
  Bottom Layer w0.21: U9.2 9.58,-6.98 v1(11.865,-9.265)
NetU9_6: U9.6 U10.6 | length 5.8
  Top Layer w0.15: v1(13.135,-7.75) U10.6
  Bottom Layer w0.15: v1(13.135,-7.75) 14.905,-9.52 U9.6
NetU9_8: U9.8 U10.8 | length 7.1
  Top Layer w0.21: v1(10.575,-4.55) 10.575,-5.855 U10.8
  Bottom Layer w0.21: v1(10.575,-4.55) 14.94,-4.55 15.05,-4.44 U9.8
STLINK_SWCLK: CN2.2 U6.37 | length 13.8
  Top Layer w0.21: CN2.2 -6.415,39.415 -3.75,36.75 U6.37
STLINK_SWDIO: CN2.4 U6.34 | length 19.7
  Top Layer w0.21: CN2.4 -5.495,44.495 -3,42 -1,42 -0.75,41.75 -0.75,39.25 -0.5,39 U6.34
STLINK_USB_D_N: CN3.2 U6.32 U8.1 U8.6 | length 8.1
  Top Layer w0.21: U6.32 0.5,39.362 1.025,39.887 1.025,40.5 0.825,40.7 U8.6 U8.1 0.825,43.425 1.025,43.625 1.025,44.25 0.65,44.625 CN3.2
STLINK_USB_D_P: CN3.3 R12.2 U6.33 U8.3 U8.4 | length 9.7
  Top Layer w0.21: R12.2 -1.165,42.65 -0.965,42.85 -0.185,42.85 U8.3 ; U6.33 0,39.37 -0.375,39.745 -0.375,40.45 -0.175,40.65 U8.4 U8.3 ; CN3.3 0,44.675 -0.375,44.3 -0.375,43.65 -0.175,43.45 U8.3
STLK_OSC_IN: C6.1 U6.5 X1.2 | length 5.3
  Top Layer w0.21: X1.2 0.25,25.2 C6.1 0.25,27.25 0.5,27.5 U6.5
STLK_OSC_OUT: C8.1 U6.6 X1.1 | length 5.3
  Top Layer w0.21: U6.6 1,27.5 1.3,27.2 C8.1 1.3,25.15 X1.1
STLK_RST: C11.2 JP2.2 U6.7 | length 14.9
  Top Layer w0.21: U6.7 1.5,28.75 2.75,27.5 3,27.5 3.725,26.775 C11.2@3.725,25.975 ; C11.2 8.148,25.7 10.998,22.85 JP2.2@12.655,22.85
STM8L001J3_T_SWIM: SB4.1 U5.1 U7.1 | length 15.1
  Top Layer w0.15: U5.1 -2.65,-4.44 ; SB4.1 -2,0.984 -1.5,0.484 -1.5,-3.3 -2.65,-4.45 -2.5,-4.6 -2.5,-9.025 -1.899,-9.626 U7.1@-1.899,-10.733
STM8L001J3_USER_B: SB5.1 U5.7 U7.7 | length 14.1
  Top Layer w0.15: U7.7@-0.635,-5.865 -0.635,-3.135 -0.5,-3 SB5.1
  Top Layer w0.21: v1(-0.635,-7.24) U7.7
  Bottom Layer w0.15: v1(-0.635,-7.24) v1@-0.62,-7.225
  Bottom Layer w0.21: v1@-0.62,-7.225 -0.59,-7.195 0.865,-7.195 0.895,-7.225 2.325,-7.225 2.57,-6.98 U5.7
STM8L001J3_USER_LED: SB6.1 U5.5 U7.5 | length 15.6
  Top Layer w0.15: SB6.1 1,1.225 1.5,0.725 1.5,-3.984 1.905,-4.402 U7.5 1.905,-8.405 2.5,-9 2.5,-10.75 U5.5 ; SB6.1@1,2.35 SB6.1
STM8L050J3_T_SWIM: SB7.1 U9.1 U10.1 | length 15.5
  Top Layer w0.15: U9.1 9.81,-4.44 ; SB7.1 9.875,1.375 11,0.25 11,-3.25 9.81,-4.44 ; U10.1@10.601,-10.835 10.601,-9.626 10,-9.025 10,-4.63 9.81,-4.44
STM8L050J3_USER_B: SB8.1 U9.7 U10.7 | length 14.2
  Top Layer w0.15: SB8.1 11.375,1.1 12,0.475 12,-2.75 11.871,-2.879 U10.7@11.871,-6.085
  Top Layer w0.21: v1(11.871,-7.121) U10.7@11.871,-6.085
  Bottom Layer w0.21: v1(11.871,-7.121) 14.879,-7.121 15.02,-6.98 U9.7
STM8L050J3_USER_LED: SB9.1 U9.5 U10.5 | length 16.2
  Top Layer w0.15: SB9.1 12.875,1.275 13.225,0.925 13.7,0.925 14,0.625 14,-3.25 14.411,-3.661 U10.5@14.411,-6.085 ; U10.5 14.405,-7.905 15,-8.5 15,-10.75 U9.5
STM8S001J3_T_SWIM: SB1.1 U1.1 U2.8 | length 11.1
  Top Layer w0.15: U1.1 -14.44,-4.44 ; U2.8 -14.44,-5.84 -14.44,-4.44 ; SB1.1 -12.875,1.1 -13.082,0.893 -13.757,0.893 -14,0.65 -14,-4 -14.44,-4.44
STM8S001J3_USER_B: SB2.1 U1.7 U2.7 | length 15.1
  Top Layer w0.15: U2.7@-13.25,-5.754 U2.7@-13.135,-5.869 ; U2.7 U2.7@-13.135,-5.869 ; U2.7@-13.129,-5.875 U2.7@-13.135,-5.869 ; SB2.1 -11.375,1.15 -12,0.525 -12,-3.275 -13.135,-4.41 U2.7@-13.135,-5.869
  Top Layer w0.21: v1(-13.135,-7.365) U2.7
  Bottom Layer w0.21: v1(-13.135,-7.365) -12.615,-7.365 -12.23,-6.98 U1.7
STM8S001J3_USER_LED: SB3.1 U1.5 U2.5 | length 15.7
  Top Layer w0.15: U2.5 -10.595,-4.244 -11,-3.839 -11,0.3 -9.875,1.425 SB3.1 ; U2.5@-10.589,-5.875 -10.589,-7 -10,-7.589 -10,-10.75 U1.5
SWIM: R1.2 R3.1 R5.1 U4.4 U6.22 U6.45 | length 20.9
  Top Layer w0.21: R1.2 -10.73,29.529 -10.625,29.634 U4.4 -9.779,29.98 -9.694,29.895 R3.1@-9.07,29.895 ; R3.1@-9.07,29.825 R3.1@-9.07,29.895 ; R5.1 -7.75,30.795 -7.938,30.607 -8.636,30.607 -9,30.243 R3.1 R3.1@-9.07,29.895 ; R5.1@-7.5,31.45 -6.142,31.45 -5.342,32.25 -4.35,32.25 -3.85,32.75 U6.45 -2,32.75 -1.857,32.893 0.634,32.893 3.491,35.75 U6.22
SWIM_IN: R5.2 U6.21 U6.43 U6.46 | length 18.7
  Top Layer w0.21: R5.2 -7.062,29.895 -5.207,31.75 -4.25,31.75 -3.75,32.25 U6.46 v1(-1.3,32.25) 0.5,32.25 3.5,35.25 U6.21 ; U6.43 v1(-1.3,33.75) v1@-1.25,33.75
  Bottom Layer w0.21: v1(-1.3,32.25) -1.3,33.7 v1@-1.25,33.75
SWIM_RST: R2.2 R4.1 R6.1 U4.6 U6.42 | length 10.9
  Top Layer w0.21: U4.6 -10.625,31.35 -10.73,31.455 R2.2 -9.779,33.02 -9.654,32.895 R4.1 -9,33.418 -8.763,33.655 -8.001,33.655 -7.75,33.906 R6.1 ; R6.1@-7.62,34.355 -3.875,34.355 -3.77,34.25 U6.42
SWIM_RST_IN: R4.2 U6.41 | length 6.6
  Top Layer w0.21: R4.2 -9.01,34.305 -9.01,34.74 -8.825,34.925 -7.15,34.925 -6.975,34.75 U6.41
T_SWIM: CN1.2 R1.1 SB1.2 SB4.2 SB7.2 U3.1 | length 64
  Top Layer w0.21: SB1.2 v1(-12.875,6.25) -14.6,6.25 -17.018,8.668 -17.018,15.75 -16.633,16.135 ; U3.1 -16.633,16.135 ; R1.1 -14.84,27.94 CN1.2 -17.018,25.762 -17.018,16.52 -16.633,16.135 ; SB4.2 v1(-2,6.25) ; SB7.2 v1(9.875,6.125)
  Bottom Layer w0.21: v1(-12.875,6.25) v1(-2,6.25) -0.354,6.25 -0.104,6.5 7.216,6.5 7.591,6.125 v1(9.875,6.125) v1@10,6.125
VDD: C1.2 C3.2 C7.2 C19.2 JP1.2 U1.4 U2.4 U3.4 U5.4 U7.4 U9.4 U10.4 | length 49.4
  Top Layer w0.3: U1.4 -16.31,-13.615 -16.025,-13.9 -10.875,-13.9 -10.55,-13.575 C3.2 -10.589,-12.736 v1(-10.589,-11.9) U2.4@-10.589,-10.693 ; C1.2@-15.215,10.3 C1.2 -15.45,9.675 -14.29,8.515 U3.4 -11.685,8.515 -10.12,10.08 JP1.2 ; U5.4@-3.81,-12.08 -2.42,-12.08 -0.5,-14 1.45,-14 1.95,-13.5 C7.2 1.95,-10.771 U7.4@1.911,-10.733 ; U9.4@8.69,-12.04 10.04,-12.04 11.75,-13.75 14,-13.75 14.45,-13.3 C19.2 14.45,-10.874 U10.4@14.411,-10.835
  Bottom Layer w0.3: v1@-10.629,-12.04 -10.589,-12 v1(-10.589,-11.9)
pads on no net: A1_1.1 A1_1.2 A1_1.3 A1_1.4 A1_1.5 A1_1.6 A1_1.7 A2_1.1 A2_1.2 A2_1.3 A2_1.4 A2_1.5 A2_1.6 A2_1.7 A3_1.1 A3_1.2 A3_1.3 A3_1.4 A3_1.5 A3_1.6 A3_1.7 CN1.1 U1.8 U3.2 U3.6 U3.8 U4.1 U4.3 U6.4 U6.11 U6.12 U6.13 U6.14 U6.15 U6.16 U6.17 U6.18 U6.19 U6.25 U6.26 U6.27 U6.28 U6.29 U6.31 U6.38 U6.40

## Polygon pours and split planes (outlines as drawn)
5V_STLINK on Top Layer "5V_STLINK_L01_P004" (solid, remove dead copper, pour order 4): 4.48,42.275 1.78,39.575 0,39.575 0,50.5 17.25,50.5 17.25,34.85 11.275,34.85 11.275,42.275
3V3_STLINK on Top Layer "3V3_STLINK_L01_P002" (solid, remove dead copper, pour order 2): -9.125,18.95 1.15,18.95 1.15,9.4 17.25,9.4 17.25,34.5 13.5,34.5 11,34.5 11,39.5 11,42 5,42 2.5,39.5 -2.5,39.5 -2.5,51 -17.25,51 -17.25,24.625 -9.125,24.625
VDD on Top Layer "VDD_L01_P006" (solid, remove dead copper, pour order 6): 0.75,9 0.75,18.5 -9.5,18.5 -9.5,24.225 -17.275,24.225 -17.275,-15 17.275,-15 17.275,9
GND on Bottom Layer "GND_L02_P000" (solid, remove dead copper, pour order 0): -19.75,0 -19.75,51.25 19,51.25 19,0.5 19,-14.5 7.75,-14.5 4.75,-14.5 -4.75,-14.5 -7.75,-14.5 -19.75,-14.5 -19.75,-2.5

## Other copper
Top Layer:
  pour cut-out: 13.775,43.875 13.775,42.375 16.025,42.375 16.025,43.875
  text "1" at 14.025,42.625 h1.5
  text ".Layer_Name" at -33.72,-38.864 h3
  text ".GTL" at 7.975,-38.864 h3
Bottom Layer:
  pour cut-out: 13.775,43.875 13.775,42.375 16.025,42.375 16.025,43.875
  text "2" at 15.775,42.625 h1.5
  text ".GBL" at -3.229,-38.896 h3
  text ".Layer_Name" at 38.085,-38.896 h3

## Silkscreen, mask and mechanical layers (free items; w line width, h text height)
Top Overlay:
  circle w0.254: c-2.075,29.75 r0.125
  circle w0.5: c8.7,-2.625 r0.125
  circle w0.5: c-3.8,-2.625 r0.125
  circle w0.5: c-16.3,-2.625 r0.125
  circle w0.21: c1.397,43.053 r0.1
  circle w0.21: c-12.446,31.496 r0.1
  circle w0.5: c-12.625,17.85 r0.125
  lines w0.21: -13.208,34.625 -13.208,32.131 -12.827,31.75
  lines w0.254: 15.024,36.107 ccw(c15,36.1) 15.025,36.1
  text "USB" at -8.2,47.775 h1.5
  text "ST-Link" at -9.2,46.275 h1.5
  text "GND" at -13.85,45.25 h1.5
  text "GND" at 13.025,45.075 h1.5
  text "COM" at 6.731,43.307 h1.5
  text "SWIM" at -17.268,21.883 h1.5
  text "MB1383A" at 2.6,20.675 h2
  text "IDD" at -9.912,20.275 h1.5
  text "STM8-SO8-DISCO" at -2.944,17.5 h2.5
  text "USER" at 7.747,8.001 h1.5
  text "GND" at -17.15,7.125 h1.5
  text "GND" at 14.175,7.125 h1.5
  text ".Layer_Name" at -33.72,-38.864 h3
  text ".GTO" at 7.975,-38.864 h3
Bottom Overlay:
  lines w0.15: -17.025,23.225 -17.025,33.45 -14.45,33.45 -14.45,23.225 ; -17.025,35.6 -17.025,45.825 -14.45,45.825 -14.45,35.6 ; -17,23.2 -14.475,23.2 ; -17,35.575 -14.475,35.575
  lines w0.2: -10.75,36.4 -10.75,42.4 10.25,42.4 10.25,36.4 -10.75,36.4
  text "RESERVED" at -14.075,36.75 h1.5 r270
  text "NRST" at -10.575,31.625 h1.5
  text "GND" at -11.257,29.025 h1.5
  text "SWIM" at -10.607,26.45 h1.5
  text "NC" at -12.314,24 h1.5
  text "SWIM" at -13.757,21.9 h1.5
  text "NC" at -10.625,-5.125 h1.5 r315
  text "IO" at 1.875,-5.125 h1.5 r315
  text "IO" at 14.375,-5.125 h1.5 r315
  text "SWIM" at -12.575,-6.9 h1.5 r315
  text "SWIM" at -0.075,-6.9 h1.5 r315
  text "SWIM" at 12.425,-6.9 h1.5 r315
  text "IO" at -10.625,-7.61 h1.5 r315
  text "IO" at 1.875,-7.61 h1.5 r315
  text "IO" at 14.375,-7.61 h1.5 r315
  text "IO" at -14.171,-8.03 h1.5 r315
  text "IO" at -1.671,-8.03 h1.5 r315
  text "IO" at 10.829,-8.03 h1.5 r315
  text "IO" at -10.625,-10.15 h1.5 r315
  text "IO" at 1.875,-10.15 h1.5 r315
  text "IO" at 14.375,-10.15 h1.5 r315
  text "GND" at -13.198,-11.3 h1.5 r315
  text "GND" at -0.698,-11.3 h1.5 r315
  text "GND" at 11.802,-11.3 h1.5 r315
  text "IO" at -10.625,-12.69 h1.5 r315
  text "IO" at 1.875,-12.69 h1.5 r315
  text "IO" at 14.375,-12.69 h1.5 r315
  text "VDD" at -13.106,-13.625 h1.5 r315
  text "VDD" at -0.606,-13.625 h1.5 r315
  text "VDD" at 11.894,-13.625 h1.5 r315
  text "STM8S001" at -9.298,-14.625 h1.5
  text "STM8L001" at 3.127,-14.625 h1.5
  text "STM8L050" at 15.719,-14.625 h1.5
  text ".GBO" at -3.229,-38.896 h3
  text ".Layer_Name" at 38.085,-38.896 h3
Top Paste:
  text ".Layer_Name" at -33.72,-38.864 h3
  text ".GTP" at 7.975,-38.864 h3
Bottom Paste:
  text ".GBP" at -3.229,-38.896 h3
  text ".Layer_Name" at 38.085,-38.896 h3
Top Solder:
  rectangle: 13.775,42.375 16.025,43.875
  text ".Layer_Name" at -33.72,-38.864 h3
  text ".GTS" at 7.975,-38.864 h3
Bottom Solder:
  rectangle: 13.775,42.375 16.025,43.875
  text ".GBS" at -3.229,-38.896 h3
  text ".Layer_Name" at 38.085,-38.896 h3
M1-Board Shape:
  lines w0.254: 7.25,-2 9.5,-2 ccw(c9.5,-1) 9.5,0 3,0 ccw(c3,-1) 3,-2 5.25,-2 5.25,-15 -5.25,-15 -5.25,-2 -3,-2 ccw(c-3,-1) -3,0 -9.5,0 ccw(c-9.5,-1) -9.5,-2 -7.25,-2 -7.25,-15 -17.75,-15 -17.75,-2 -15.5,-2 ccw(c-15.5,-1) -15.5,0 -17.75,0 -17.75,50 17.75,50 17.75,0 15.5,0 ccw(c15.5,-1) 15.5,-2 17.75,-2 17.75,-15 7.25,-15 7.25,-2 ; 7.25,-2 7.25,-2
M2-Board Dimensions:
  text ".Layer_Name" at -33.72,-38.864 h3
  text ".GM2" at 7.975,-38.864 h3
M14-Top Assembly:
  text ".Layer_Name" at -33.72,-38.864 h3
  text ".GM14" at 7.975,-38.864 h3
M15-Bottom Assembly:
  text ".GM15" at -3.229,-38.896 h3
  text ".Layer_Name" at 38.085,-38.896 h3
Drill Drawing:
  text ".Legend" at -42.7,61.525 h1.2
  text ".Layer_Name" at -33.72,-38.864 h3
  text ".DRL" at 7.975,-38.864 h3
M20-Top Title Box:
  circle w0.254: c44.284,-45.584 r1.3
  region: 29.806,-46.677 19.05,-46.677 20.043,-44.185 27.901,-44.185 28.35,-43.425 30.558,-45.974
  region: 43.809,-38.348 28.282,-38.348 27.588,-40.123 26.377,-41.348 24.98,-39.488 24.98,-37.837 26.123,-36.44 27.559,-36.062 43.809,-36.062
  lines w0.254: 20.043,-44.185 28.835,-44.185 25.769,-40.647 cw(c27.573,-38.703) 27.813,-36.062 44.577,-36.062 43.815,-38.348 ; 23.357,-35.815 cw(c25.783,-36.785) 26.02,-34.183 ; 23.396,-35.782 19.05,-46.677 38.373,-46.677 ccw(c38.621,-43.943) 41.171,-44.963 ; 25.136,-39.717 30.558,-45.974 ; 25.39,-39.717 30.695,-45.838 ; 25.39,-39.463 30.695,-45.584 ; 25.488,-38.348 38.481,-38.348 ; 25.517,-39.336 30.822,-45.457 ; 25.644,-39.209 30.949,-45.33 ; 25.771,-39.082 31.076,-45.203 ; 25.898,-38.955 31.203,-45.076 ; 25.953,-37.003 31.258,-43.124 ; 26.021,-34.183 45.471,-34.183 41.171,-44.96 ; 26.025,-38.828 31.276,-44.886 ; 26.025,-38.574 31.33,-44.695 ; 26.025,-38.32 31.33,-44.441 ; 26.025,-37.431 31.33,-43.552 ; 26.152,-38.193 31.457,-44.314 ; 26.152,-37.812 31.457,-43.933 ; 27.524,-44.198 ccw(c27.629,-43.663) 27.926,-43.206 ; 28.61,-38.334 ccw(c28.584,-38.902) 28.254,-39.364 30.619,-42.093 cw(c28.815,-44.036) 29.548,-46.585 ; 34.892,-46.473 37.781,-38.094 ; 35.114,-46.423 37.983,-38.103 ; 35.241,-46.423 38.11,-38.103 ; 35.495,-46.423 38.364,-38.103 ; 35.749,-46.423 38.618,-38.103 ; 36.003,-46.423 38.872,-38.103 ; 36.257,-46.423 39.126,-38.103 ; 36.511,-46.423 39.38,-38.103 ; 36.765,-46.423 39.634,-38.103 ; 37.019,-46.423 39.888,-38.103 ; 37.227,-46.473 40.117,-38.094 ; 40.117,-38.348 43.809,-38.348 ; 43.141,-38.345 43.903,-36.059 ; 43.307,-38.348 44.069,-36.062 ; 43.561,-38.348 44.323,-36.062
  lines w0.3: -42.72,-45.564 17.28,-45.564 ; -42.72,-40.564 17.28,-40.564 ; -42.72,-35.564 17.28,-35.564 ; -2.72,-50.564 -2.72,-35.564 ; 17.28,-50.564 17.28,-30.564 ; 34.892,-46.473 37.227,-46.473 ; -42.72,-50.564 47.28,-50.564 47.28,-30.564 -42.72,-30.564 -42.72,-50.564
  text "Project: '.Board_Name'" at -41.72,-33.78 h3
  text "Layer:" at -41.72,-38.864 h3
  text "Gerber:" at -1.731,-38.864 h3
  text "Variant: '.VariantName'" at -41.72,-43.864 h3
  text "Ref: '.Board_Reference'" at -1.604,-43.864 h3
  text "R" at 43.776,-46.346 h1.52
  text "Date: '.Board_Document_Date'" at -41.72,-48.864 h3
  text "Rev: '.Board_PCB_Revision'" at -1.661,-48.864 h3
M21-Bottom Title Box:
  circle w0.254: c-39.537,-45.584 r1.3
  region: -39.063,-38.348 -23.535,-38.348 -22.841,-40.123 -21.63,-41.348 -20.233,-39.488 -20.233,-37.837 -21.376,-36.44 -22.812,-36.062 -39.063,-36.062
  region: -25.059,-46.677 -14.303,-46.677 -15.297,-44.185 -23.154,-44.185 -23.603,-43.425 -25.812,-45.974
  lines w0.254: -39.576,-36.062 -38.814,-38.348 ; -39.322,-36.062 -38.56,-38.348 ; -39.156,-36.059 -38.394,-38.345 ; -39.068,-38.348 -39.83,-36.062 -23.066,-36.062 cw(c-22.826,-38.703) -21.023,-40.647 -24.089,-44.185 -15.297,-44.185 ; -39.063,-38.348 -35.37,-38.348 ; -36.425,-44.96 -40.724,-34.183 -21.275,-34.183 ; -36.424,-44.963 ccw(c-33.875,-43.943) -33.626,-46.677 -14.303,-46.677 -18.65,-35.782 ; -35.37,-38.094 -32.481,-46.473 ; -35.142,-38.103 -32.272,-46.423 ; -34.888,-38.103 -32.018,-46.423 ; -34.634,-38.103 -31.764,-46.423 ; -34.38,-38.103 -31.51,-46.423 ; -34.126,-38.103 -31.256,-46.423 ; -33.872,-38.103 -31.002,-46.423 ; -33.734,-38.348 -20.741,-38.348 ; -33.618,-38.103 -30.748,-46.423 ; -33.364,-38.103 -30.494,-46.423 ; -33.237,-38.103 -30.367,-46.423 ; -33.034,-38.094 -30.145,-46.473 ; -26.71,-44.314 -21.405,-38.193 ; -26.71,-43.933 -21.405,-37.812 ; -26.583,-44.695 -21.278,-38.574 ; -26.583,-44.441 -21.278,-38.32 ; -26.583,-43.552 -21.278,-37.431 ; -26.529,-44.886 -21.278,-38.828 ; -26.511,-43.124 -21.206,-37.003 ; -26.456,-45.076 -21.151,-38.955 ; -26.329,-45.203 -21.024,-39.082 ; -26.202,-45.33 -20.897,-39.209 ; -26.075,-45.457 -20.77,-39.336 ; -25.948,-45.838 -20.643,-39.717 ; -25.948,-45.584 -20.643,-39.463 ; -25.812,-45.974 -20.389,-39.717 ; -24.801,-46.585 cw(c-24.069,-44.036) -25.872,-42.093 -23.507,-39.364 ccw(c-23.838,-38.902) -23.864,-38.334 ; -23.18,-43.206 ccw(c-22.882,-43.663) -22.777,-44.198 ; -21.273,-34.183 cw(c-21.037,-36.785) -18.611,-35.815
  lines w0.3: -32.481,-46.473 -30.145,-46.473 ; -12.72,-50.564 -12.72,-30.564 ; -12.72,-45.564 47.28,-45.564 ; -12.72,-40.564 47.28,-40.564 ; -12.72,-35.564 47.28,-35.564 ; 7.28,-50.564 7.28,-35.564 ; -42.72,-50.564 -42.72,-30.564 47.28,-30.564 47.28,-50.564 -42.72,-50.564
  text "Project: '.Board_Name'" at 46.086,-33.78 h3
  text "Gerber:" at 6.097,-38.864 h3
  text "Layer:" at 46.085,-38.864 h3
  text "Ref: '.Board_Reference'" at 6.097,-43.864 h3
  text "Variant: '.VariantName'" at 46.086,-43.864 h3
  text "R" at -39.029,-46.346 h1.52
  text "Rev: '.Board_PCB_Revision'" at 6.154,-48.864 h3
  text "Date: '.Board_Document_Date'" at 46.086,-48.864 h3

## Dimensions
17.75,50 to 17.75,-15 on M2-Board Dimensions
-17.75,50 to 17.75,50 on M2-Board Dimensions
-17.75,0 to -17.75,50 on M2-Board Dimensions
-17.75,-2 to -17.75,-15 on M2-Board Dimensions
-17.75,0 to -17.75,-2 on M2-Board Dimensions
-17.75,-15 to -7.25,-15 on M2-Board Dimensions
-5.25,-15 to 5.25,-15 on M2-Board Dimensions
7.25,-15 to 17.75,-15 on M2-Board Dimensions
-7.25,-15 to -5.25,-15 on M2-Board Dimensions
5.25,-15 to 7.25,-15 on M2-Board Dimensions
